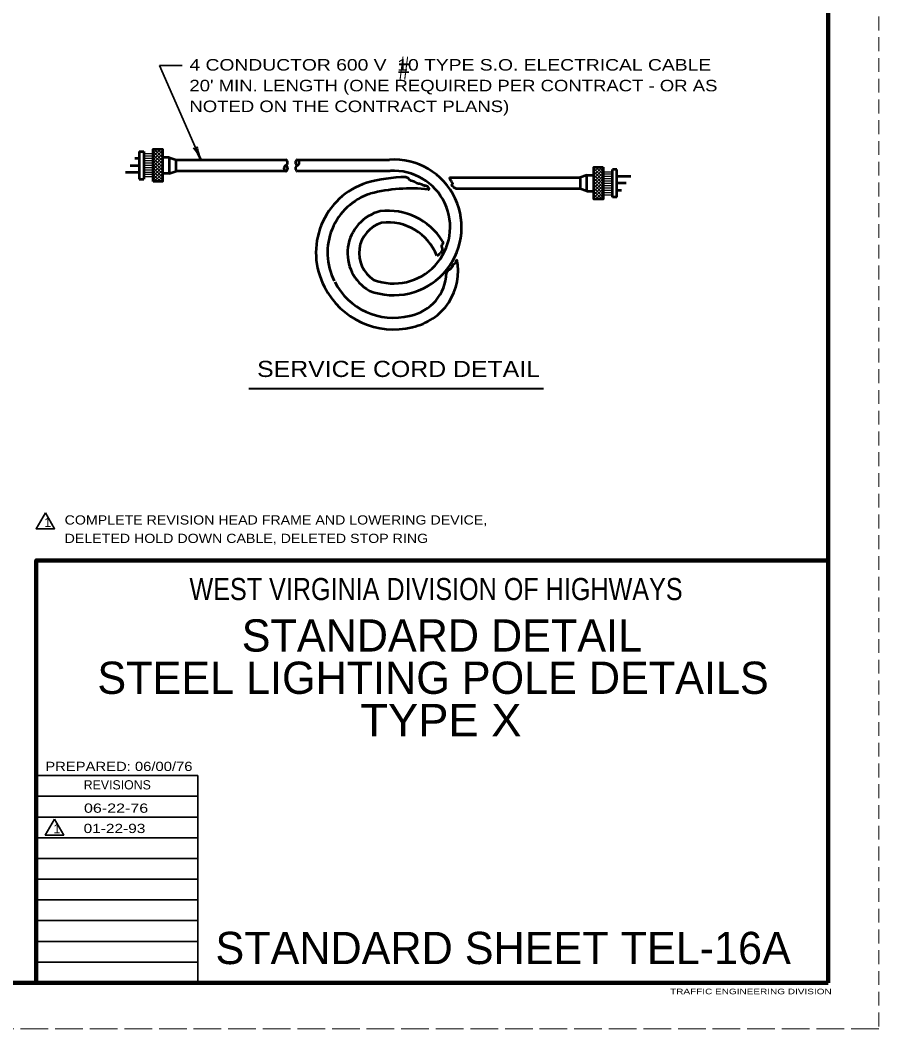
# Model space of a CAD drawing. Extents: x -1 to 679, y 0 to 440.
# Drawn here: x 492.5 to 678.6, y -0.4 to 218.4 of the extents above; entities that cross this region are included whole.
import ezdxf
from ezdxf.enums import TextEntityAlignment as Align

# ---------------------------------------------------------------- set-up
doc = ezdxf.new("R2010")
doc.units = 0
doc.linetypes.add('LONG_DASHED', pattern=[7.5, 6, -1.5])
doc.linetypes.add('MEDIUM_DASHED', pattern=[4.5, 3, -1.5])
doc.layers.add('1', color=7, linetype='Continuous', lineweight=35)
doc.layers.add('61', color=7, linetype='Continuous', lineweight=35)

msp = doc.modelspace()

# ---------------------------------------------------------------- linework, layer by layer
at = {"layer": '1', "linetype": 'MEDIUM_DASHED', "lineweight": 13}
msp.add_line((678.595, 439.645), (678.575, -0.375), dxfattribs=at)
at = {"layer": '1'}
for p, q in [((531.609, 188.104), (522.704, 208.555)), ((527.561, 208.555), (522.704, 208.555)), ((530.975, 50.045), (495.995, 50.045)), ((530.975, 45.545), (495.995, 45.545)), ((530.975, 41.045), (495.995, 41.045)), ((530.975, 36.525), (495.995, 36.525)), ((530.975, 32.045), (495.995, 32.045)), ((530.975, 27.565), (495.995, 27.565)), ((530.975, 23.065), (495.995, 23.065)), ((530.975, 18.565), (495.995, 18.565)), ((530.975, 14.045), (495.995, 14.045))]:
    msp.add_line(p, q, dxfattribs=at)
at = {"layer": '1', "lineweight": 25}
for p, q in [((521.309, 190.182), (521.481, 190.354)), ((521.309, 189.475), (522.188, 190.354)), ((521.309, 188.767), (522.895, 190.354)), ((523.309, 188.581), (521.535, 190.354)), ((523.309, 189.288), (522.242, 190.354)), ((523.309, 189.995), (522.95, 190.354)), ((521.309, 189.354), (519.309, 189.354)), ((521.309, 188.854), (519.309, 188.854)), ((521.309, 188.354), (519.309, 188.354)), ((521.309, 188.06), (523.309, 190.06)), ((523.309, 187.874), (521.309, 189.874)), ((521.309, 187.353), (523.309, 189.353)), ((523.309, 187.167), (521.309, 189.167)), ((521.309, 186.646), (523.309, 188.646)), ((523.309, 186.46), (521.309, 188.46)), ((521.309, 187.854), (519.309, 187.854)), ((521.309, 187.354), (519.309, 187.354)), ((521.309, 186.854), (519.309, 186.854)), ((521.309, 186.354), (519.309, 186.354)), ((521.309, 185.939), (523.309, 187.939)), ((523.309, 185.753), (521.309, 187.753)), ((521.309, 185.232), (523.309, 187.232)), ((523.309, 185.046), (521.309, 187.046)), ((521.309, 184.525), (523.309, 186.525)), ((523.309, 184.338), (521.309, 186.338)), ((618.599, 186.503), (616.843, 184.747)), ((617.892, 186.503), (616.843, 185.454)), ((617.185, 186.503), (616.843, 186.161)), ((616.843, 186.226), (618.843, 184.226)), ((618.843, 186.04), (616.843, 184.04)), ((617.273, 186.503), (618.843, 184.933)), ((617.98, 186.503), (618.843, 185.64)), ((618.687, 186.503), (618.843, 186.347)), ((521.309, 185.854), (519.309, 185.854)), ((521.309, 185.354), (519.309, 185.354)), ((521.309, 184.854), (519.309, 184.854)), ((521.309, 184.354), (519.309, 184.354)), ((521.309, 183.818), (523.309, 185.818)), ((523.309, 183.631), (521.309, 185.631)), ((522.879, 183.354), (521.309, 184.924)), ((522.171, 183.354), (521.309, 184.217)), ((521.552, 183.354), (523.309, 185.111)), ((522.259, 183.354), (523.309, 184.404)), ((616.843, 185.519), (618.843, 183.519)), ((618.843, 185.332), (616.843, 183.332)), ((616.843, 184.812), (618.843, 182.812)), ((618.843, 184.625), (616.843, 182.625)), ((616.843, 184.105), (618.843, 182.105)), ((618.843, 183.918), (616.843, 181.918)), ((618.843, 185.503), (620.843, 185.503)), ((618.843, 185.003), (620.843, 185.003)), ((618.843, 184.503), (620.843, 184.503)), ((618.843, 184.003), (620.843, 184.003)), ((521.464, 183.354), (521.309, 183.51)), ((522.967, 183.354), (523.309, 183.696)), ((616.843, 183.398), (618.843, 181.398)), ((618.843, 183.211), (616.843, 181.211)), ((616.843, 182.69), (618.843, 180.69)), ((618.843, 182.504), (616.843, 180.504)), ((616.843, 181.983), (618.843, 179.983)), ((618.843, 181.797), (616.843, 179.797)), ((618.843, 183.503), (620.843, 183.503)), ((618.843, 183.003), (620.843, 183.003)), ((618.843, 182.503), (620.843, 182.503)), ((618.843, 182.003), (620.843, 182.003)), ((616.843, 181.276), (618.616, 179.503)), ((616.843, 180.569), (617.909, 179.503)), ((616.843, 179.862), (617.202, 179.503)), ((618.843, 181.09), (617.256, 179.503)), ((618.843, 180.383), (617.963, 179.503)), ((618.843, 179.676), (618.67, 179.503)), ((618.843, 181.503), (620.843, 181.503)), ((618.843, 181.003), (620.843, 181.003)), ((618.843, 180.503), (620.843, 180.503))]:
    msp.add_line(p, q, dxfattribs=at)
at = {"layer": '1', "lineweight": 53}
for p, q in [((518.309, 188.354), (517.309, 188.354)), ((518.309, 189.854), (518.309, 183.854)), ((518.309, 189.854), (519.309, 189.854)), ((519.309, 189.854), (519.309, 183.854)), ((524.809, 188.604), (523.309, 188.604)), ((524.809, 188.604), (524.809, 185.104)), ((524.809, 188.604), (526.309, 188.104)), ((516.309, 186.854), (518.309, 186.854)), ((552.559, 188.104), (572.559, 188.104)), ((620.843, 180.003), (620.843, 186.003)), ((621.843, 186.003), (620.843, 186.003)), ((621.843, 180.003), (621.843, 186.003)), ((518.309, 185.354), (515.309, 185.354)), ((518.309, 183.854), (519.309, 183.854)), ((524.809, 185.104), (523.309, 185.104)), ((524.809, 185.104), (526.309, 185.604)), ((550.059, 185.604), (526.309, 185.604)), ((572.712, 185.604), (552.559, 185.604)), ((615.343, 184.753), (613.843, 184.253)), ((615.343, 181.253), (615.343, 184.753)), ((615.343, 184.753), (616.843, 184.753)), ((621.843, 184.503), (624.843, 184.503)), ((615.343, 181.253), (613.843, 181.753)), ((623.843, 183.003), (621.843, 183.003)), ((615.343, 181.253), (616.843, 181.253)), ((621.843, 180.003), (620.843, 180.003)), ((621.843, 181.503), (622.843, 181.503))]:
    msp.add_line(p, q, dxfattribs=at)
at = {"layer": '1', "lineweight": 40}
msp.add_line((542.028, 138.49), (605.888, 138.49), dxfattribs=at)
at = {"layer": '1', "lineweight": 53}
for points in [[(521.309, 183.354), (521.309, 190.354), (523.309, 190.354), (523.309, 183.354)], [(618.843, 186.503), (618.843, 179.503), (616.843, 179.503), (616.843, 186.503)]]:
    msp.add_lwpolyline(points, close=True, dxfattribs=at)
for points in [[(526.309, 185.604), (526.309, 188.104), (550.059, 188.104)], [(585.566, 184.253), (613.843, 184.253), (613.843, 181.753), (587.365, 181.753)]]:
    msp.add_lwpolyline(points, dxfattribs=at)
at = {"layer": '1'}
for points in [[(497.944, 111.522), (495.944, 108.057), (499.944, 108.057)], [(499.922, 45.104), (497.922, 41.64), (501.922, 41.64)]]:
    msp.add_lwpolyline(points, close=True, dxfattribs=at)
at = {"layer": '1', "lineweight": 158}
msp.add_lwpolyline([(495.975, 9.605), (495.975, 101.185), (667.635, 101.185)], dxfattribs=at)
at = {"layer": '1'}
msp.add_lwpolyline([(530.975, 9.565), (530.975, 54.525), (495.995, 54.525)], dxfattribs=at)
at = {"layer": '1', "lineweight": 53}
for centre, radius, start, end in [((573.46, 173.42), 14.712, 248.92664, 93.51269), ((550.333, 186.229), 0.665, 110.01746, 249.98254), ((549.823, 186.229), 0.668, 290.62029, 69.37971), ((549.73, 187.479), 0.706, 297.75189, 62.24811), ((552.86, 187.479), 0.694, 115.76424, 244.23576), ((552.86, 186.229), 0.694, 115.76424, 244.23576), ((552.286, 187.479), 0.694, 295.76424, 64.23576), ((577.127, 147.163), 37.193, 91.64258, 104.90932), ((573.469, 173.459), 12.212, 248.92664, 93.51269), ((572.53, 167.95), 15.941, 108.16556, 207.79267), ((577.127, 147.163), 34.693, 83.67368, 104.54428), ((572.53, 167.95), 13.441, 108.16556, 207.20957), ((572.804, 167.834), 9.369, 104.10799, 240.35478), ((572.227, 163.185), 13.842, 31.61739, 97.08099), ((572.804, 167.834), 6.869, 106.73846, 237.14925), ((572.224, 163.158), 11.342, 21.22901, 97.08099), ((575.054, 163.927), 12.358, 281.24918, 11.93102), ((575.054, 163.927), 9.858, 281.24918, 357.69166), ((573.407, 168.073), 16.77, 206.76656, 284.17816), ((573.407, 168.073), 14.27, 206.76656, 284.17816)]:
    msp.add_arc(centre, radius, start, end, dxfattribs=at)
at = {"layer": '1', "lineweight": 40}
for centre, major_axis, ratio, start_param, end_param in [((530.92, 188.994), (0.856, -1.575), 0.122415, 0.8963533, 3.1415927), ((531.355, 189.216), (0.54, -1.681), 0.07063, 3.1407148, 5.41811)]:
    msp.add_ellipse(centre, major_axis=major_axis, ratio=ratio, start_param=start_param, end_param=end_param, dxfattribs=at)
at = {"layer": '1', "lineweight": 53}
for points in [[(580.95, 181.644), (581.096, 181.69), (580.784, 182.27), (580.026, 182.47), (579.29, 182.805), (578.421, 183.006), (577.975, 183.296), (577.061, 183.585), (576.726, 183.942), (576.061, 184.34)], [(587.365, 181.753), (586.781, 181.913), (586.38, 182.18), (586.068, 182.515), (586.246, 182.961), (585.956, 183.362), (585.8, 183.608), (585.566, 184.253)], [(584.014, 170.441), (584.1, 169.927), (583.908, 169.602), (583.804, 169.262), (583.967, 168.804), (583.848, 168.316), (583.331, 167.607), (582.796, 167.264)], [(587.145, 166.482), (586.907, 166.025), (586.759, 165.612), (586.36, 165.272), (586.094, 164.828), (585.651, 164.34), (585.415, 164.163), (585.03, 163.838), (584.904, 163.53)]]:
    msp.add_spline(points, degree=3, dxfattribs=at)
at = {"layer": '61', "lineweight": 158}
for p, q in [((667.615, 429.645), (667.635, 9.605)), ((667.635, 9.605), (28.575, 9.625))]:
    msp.add_line(p, q, dxfattribs=at)
at = {"layer": '61', "linetype": 'LONG_DASHED', "lineweight": 13}
msp.add_line((678.575, -0.375), (-1.485, -0.395), dxfattribs=at)

# ---------------------------------------------------------------- texts
at = {"layer": '1'}
for s, height, width, p in [('#', 5, 0.65, (575.651, 205.447)), ('SERVICE CORD DETAIL', 3.5, 1.15, (574.494, 140.976)), ('WEST VIRGINIA DIVISION OF HIGHWAYS', 4.795, 0.85, (582.624, 92.585)), ('TYPE X', 6.993, 1.05, (583.676, 63.072)), ('06-22-76', 2, 1.3, (513.275, 46.465)), ('01-22-93', 2, 1.25, (512.925, 42.065))]:
    msp.add_text(s, height=height, dxfattribs=dict(at, width=width)).set_placement(p, align=Align.CENTER)
for s, height, width, p in [('4 CONDUCTOR 600 V  10 TYPE S.O. ELECTRICAL CABLE', 2.5, 1.25, (529.17, 207.424)), ("20' MIN. LENGTH (ONE REQUIRED PER CONTRACT - OR AS", 2.5, 1.2, (529.17, 202.924)), ('NOTED ON THE CONTRACT PLANS)', 2.5, 1.2, (529.17, 198.424)), ('COMPLETE REVISION HEAD FRAME AND LOWERING DEVICE,', 2, 1.15, (502.121, 108.972)), ('DELETED HOLD DOWN CABLE, DELETED STOP RING', 2, 1.15, (502.121, 104.972)), ('PREPARED: 06/00/76', 1.998, 1.2, (497.935, 55.525)), ('TRAFFIC ENGINEERING DIVISION', 1.2, 1.35, (633.355, 7.105))]:
    msp.add_text(s, height=height, dxfattribs=dict(at, width=width)).set_placement(p)
for s, height, p in [('1', 2, (498.458, 108.432)), ('STANDARD DETAIL', 6.993, (583.892, 81.425)), ('STEEL LIGHTING POLE DETAILS', 6.993, (581.977, 72.249)), ('1', 2, (500.436, 42.015))]:
    msp.add_text(s, height=height, dxfattribs=at).set_placement(p, align=Align.CENTER)
for s, height, p in [('REVISIONS', 1.998, (506.255, 51.525)), ('STANDARD SHEET TEL-16A', 6.993, (534.815, 13.645))]:
    msp.add_text(s, height=height, dxfattribs=at).set_placement(p)

doc.saveas('drawing.dxf')
